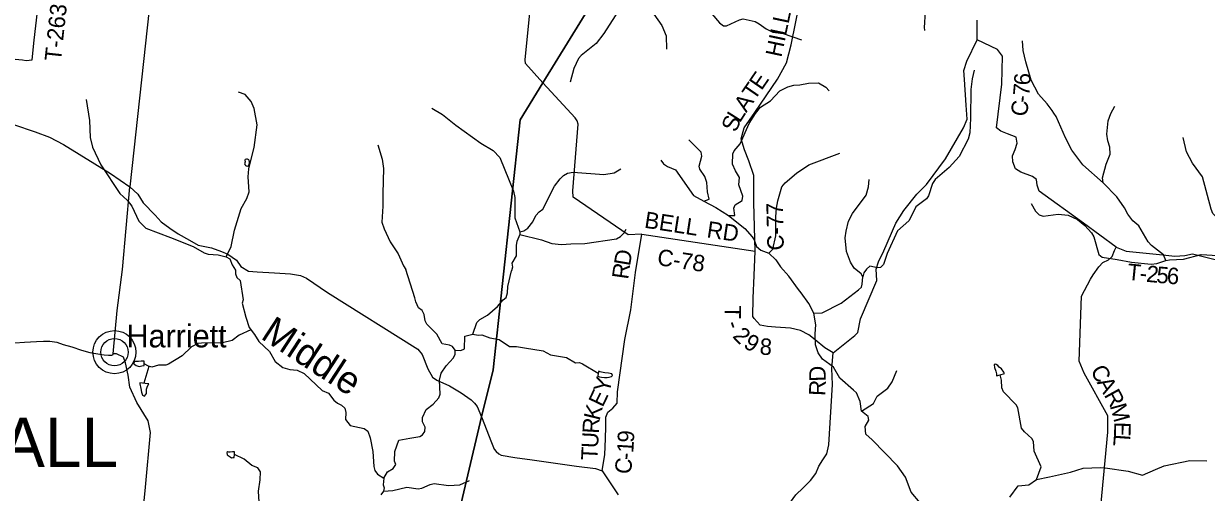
# Model space of a CAD drawing. Extents: x 1525783 to 1900577, y 218250 to 627376.
# Drawn here: x 1686297 to 1707878, y 407202 to 415754 of the extents above; entities that cross this region are included whole.
import ezdxf

# ---------------------------------------------------------------- set-up
doc = ezdxf.new("R2010")
doc.units = 0
for name, color, linetype in [('GM_X_County_Road', 7, 'Continuous'), ('GM_X_County_Road_Text', 7, 'Continuous'), ('GM_X_Minor_Lake', 7, 'Continuous'), ('GM_X_Minor_River', 7, 'Continuous'), ('GM_X_Minor_River_Text', 7, 'Continuous'), ('GM_X_State_Route', 7, 'Continuous'), ('GM_X_Township', 7, 'Continuous'), ('GM_X_Township_Road', 7, 'Continuous'), ('GM_X_Township_Road_Text', 7, 'Continuous'), ('GM_X_Township_Text', 7, 'Continuous'), ('GM_X_Unincorporated', 7, 'Continuous'), ('GM_X_Unincorporated_Location', 7, 'Continuous'), ('GM_X_Unincorporated_Text', 7, 'Continuous')]:
    doc.layers.add(name, color=color, linetype=linetype)

msp = doc.modelspace()

# ---------------------------------------------------------------- linework, layer by layer
at = {"layer": 'GM_X_County_Road'}
for points in [[(1695922, 414510), (1695772, 414672), (1695455, 415030), (1695450, 415092), (1695544, 416074), (1695641, 417095), (1695592, 417148), (1694627, 417269), (1694779, 418524), (1694799, 418859), (1694750, 418990), (1694323, 419546), (1692590, 421859)], [(1699644, 411605), (1699623, 412489), (1699619, 412983), (1699529, 413250), (1699452, 413451), (1699391, 413651), (1699445, 413854), (1699642, 414132), (1700054, 414743), (1700219, 415040), (1700299, 415367), (1700476, 416244)], [(1683229, 415931), (1683600, 415673), (1683898, 415507), (1684581, 415018), (1684679, 414918), (1684821, 414800), (1684888, 414749), (1684947, 414698), (1685278, 414411), (1685698, 414044), (1685829, 413971), (1686112, 413914), (1686509, 413780), (1686769, 413685), (1687024, 413547), (1687879, 413021), (1688235, 412775)], [(1705874, 406102), (1706079, 408301), (1706080, 408599), (1705647, 409379), (1705556, 409594), (1705599, 410784), (1705761, 411092), (1705811, 411173), (1705917, 411319), (1705987, 411394), (1706090, 411447), (1706160, 411508), (1706200, 411617), (1706232, 411679), (1705635, 412112), (1704826, 412697), (1704789, 412807), (1704777, 412909), (1704708, 412963), (1704490, 413043), (1704397, 413103), (1704346, 413231), (1704341, 413341), (1704392, 413456), (1704428, 413572), (1704407, 413683), (1704248, 413743), (1704127, 413792), (1704050, 413856), (1704148, 414652), (1704156, 415159), (1704064, 415280), (1703696, 415457), (1703693, 415819)], [(1696852, 407597), (1696903, 407893), (1696917, 408177), (1696922, 408404), (1696923, 408574), (1696956, 408667), (1697046, 408737), (1697129, 408832), (1697136, 409037), (1697268, 409989), (1697377, 410533), (1697460, 411211), (1697578, 411916), (1697329, 411902), (1696327, 412591), (1696319, 412702), (1696417, 413923), (1696398, 413982), (1696358, 414036), (1695922, 414510)], [(1689376, 402305), (1689315, 402509), (1689280, 402641), (1689079, 403395), (1688943, 403934), (1688868, 404164), (1688526, 404763), (1688383, 405107), (1688311, 405205), (1688519, 407298), (1688611, 408295), (1688572, 408507), (1688365, 408841), (1688235, 409123), (1688204, 409341), (1688156, 409567), (1688118, 409667), (1687991, 409731), (1687933, 409730), (1688006, 410518), (1688100, 411267), (1688235, 412775)], [(1697578, 411916), (1699644, 411605)]]:
    msp.add_lwpolyline(points, dxfattribs=at)
at = {"layer": 'GM_X_Minor_Lake'}
for points in [[(1690332, 413263), (1690334, 413253), (1690340, 413243), (1690336, 413229), (1690332, 413219), (1690330, 413209), (1690328, 413197), (1690336, 413177), (1690348, 413167), (1690358, 413163), (1690370, 413161), (1690382, 413157), (1690400, 413161), (1690404, 413171), (1690410, 413189), (1690414, 413199), (1690416, 413211), (1690418, 413221), (1690416, 413231), (1690414, 413249), (1690412, 413259), (1690404, 413269), (1690380, 413281), (1690362, 413281)], [(1690362, 413281), (1690340, 413274), (1690332, 413263)], [(1688498, 409547), (1688497, 409593), (1688441, 409597), (1688393, 409592), (1688345, 409592), (1688315, 409588), (1688310, 409548), (1688352, 409514), (1688406, 409497), (1688452, 409513), (1688482, 409519)], [(1688482, 409519), (1688496, 409518), (1688498, 409547)], [(1696783, 409376), (1696772, 409325), (1696806, 409312), (1696844, 409306), (1696894, 409297), (1696946, 409299), (1696982, 409302), (1697022, 409316), (1697040, 409334), (1697030, 409364), (1696969, 409379), (1696903, 409381), (1696839, 409396), (1696815, 409402), (1696795, 409416)], [(1696795, 409416), (1696783, 409376)], [(1704116, 409349), (1704194, 409370), (1704182, 409396), (1704137, 409456), (1704099, 409487), (1704071, 409515), (1704043, 409535), (1704022, 409542), (1704009, 409532), (1704013, 409480), (1704034, 409413), (1704046, 409363), (1704051, 409331)], [(1688514, 409190), (1688417, 409198), (1688419, 409181)], [(1688419, 409181), (1688436, 409097), (1688447, 409031), (1688466, 408978), (1688500, 408958), (1688539, 409006), (1688541, 409084), (1688556, 409142), (1688580, 409183), (1688514, 409190)], [(1704051, 409331), (1704116, 409349)], [(1690146, 407893), (1690142, 407941), (1690108, 407939), (1690068, 407938), (1690040, 407938), (1690022, 407940), (1690006, 407930), (1690008, 407884), (1690050, 407864), (1690067, 407852), (1690091, 407833), (1690117, 407837)], [(1690117, 407837), (1690141, 407840), (1690146, 407893)]]:
    msp.add_lwpolyline(points, dxfattribs=at)
at = {"layer": 'GM_X_Minor_River'}
for points in [[(1702119, 419487), (1702102, 419417), (1702264, 418875), (1702426, 418559), (1702534, 418306), (1702783, 417903), (1702845, 417667), (1702853, 417550), (1702819, 417483), (1702721, 417362), (1702664, 417245), (1702653, 417060), (1702734, 416802), (1702731, 416742), (1702671, 416537), (1702652, 416386), (1702659, 416308), (1702712, 416131), (1702739, 415891), (1702737, 415769), (1702731, 415691), (1702736, 415629)], [(1698814, 417899), (1698716, 417809), (1698720, 417534), (1698813, 417354), (1698859, 417221), (1698836, 417042), (1698848, 416974), (1698965, 416689), (1698979, 416580), (1698952, 416408), (1698841, 416079), (1698832, 416003), (1698855, 415933), (1698992, 415768), (1699065, 415716), (1699125, 415713), (1699358, 415827), (1699424, 415842), (1699648, 415794), (1699719, 415751), (1699846, 415662), (1699965, 415602), (1700153, 415574), (1700490, 415458)], [(1698720, 417534), (1698605, 417360), (1698418, 417126), (1698035, 416718), (1697964, 416653), (1697522, 416490), (1697406, 416392), (1697197, 416069), (1696881, 415575), (1696741, 415391), (1696469, 415171), (1696424, 415120), (1696338, 414935), (1696271, 414685)], [(1697964, 416653), (1697832, 416547), (1697630, 416282), (1697595, 416210), (1697588, 416156), (1697607, 416100), (1697794, 415930), (1697945, 415720), (1698019, 415532), (1698025, 415292)], [(1707140, 411431), (1707093, 411536), (1706880, 411709), (1706819, 411776), (1706648, 412066), (1706536, 412154), (1706446, 412276), (1706386, 412396), (1706245, 412593), (1705996, 412852), (1705627, 413180), (1705421, 413448), (1705307, 413669), (1705136, 414059), (1705095, 414120), (1705064, 414171), (1704976, 414293), (1704817, 414470), (1704684, 414725), (1704584, 415058), (1704535, 415265), (1704521, 415440)], [(1703639, 414908), (1703602, 414746), (1703582, 414554), (1703574, 414031), (1703565, 413760), (1703529, 413644), (1703366, 413330), (1703186, 413131), (1702932, 412909), (1702882, 412838), (1702808, 412612), (1702771, 412561), (1702577, 412412), (1702521, 412296), (1702446, 412157), (1702240, 411972), (1702052, 411562), (1701988, 411359), (1701929, 411306), (1701877, 411297), (1701737, 411327), (1701674, 411272), (1701630, 411205), (1701609, 411137)], [(1699158, 412254), (1699271, 412256), (1699253, 412387), (1699280, 412451), (1699410, 412530), (1699418, 412605), (1699347, 412816), (1699360, 412947), (1699288, 413068), (1699232, 413192), (1699236, 413380), (1699259, 413432), (1699369, 413560), (1699535, 413930), (1699609, 414048), (1699652, 414113), (1699741, 414230), (1699924, 414349), (1700097, 414526), (1700239, 414600), (1700352, 414632), (1700458, 414638), (1700619, 414669), (1700802, 414674), (1700933, 414598), (1700993, 414528)], [(1687438, 414373), (1687497, 413987), (1687513, 413679), (1687554, 413500), (1687706, 413178), (1688051, 412655), (1688185, 412534), (1688273, 412424), (1688401, 412153), (1688524, 412022), (1688978, 411851), (1689390, 411688), (1689588, 411572), (1689662, 411546), (1689848, 411537), (1689992, 411502), (1690062, 411461), (1690100, 411352), (1690161, 411255)], [(1689992, 411502), (1690086, 411691), (1690146, 411987), (1690267, 412382), (1690369, 412567), (1690413, 412686), (1690393, 412961), (1690407, 413108), (1690453, 413309), (1690501, 413497), (1690561, 413909), (1690506, 414209), (1690448, 414337), (1690337, 414461), (1690219, 414505)], [(1693746, 414213), (1693942, 414099), (1694183, 413900), (1694640, 413571), (1694862, 413439), (1694988, 413314), (1695233, 412700), (1695257, 412585), (1695262, 412210), (1695352, 411957), (1695351, 411907), (1695296, 411780), (1695283, 411710), (1695285, 411515), (1695207, 411384), (1695217, 411312), (1695196, 411242)], [(1705996, 412852), (1705981, 412940), (1706048, 413192), (1706120, 413373), (1706116, 413500), (1706080, 413617), (1706064, 413737), (1706089, 413982), (1706138, 414117), (1706210, 414250)], [(1692757, 413545), (1692841, 413284), (1692865, 413109), (1692849, 412658), (1692854, 412422), (1692833, 412135), (1692873, 412012), (1692985, 411775), (1693131, 411552), (1693227, 411336), (1693272, 411269)], [(1698706, 412517), (1698807, 412553), (1698774, 412688), (1698765, 412857), (1698725, 412968), (1698633, 413102), (1698626, 413152), (1698672, 413336), (1698657, 413407), (1698435, 413637)], [(1708341, 411440), (1708371, 411453), (1708372, 411640), (1708354, 411712), (1708309, 411787), (1708201, 411892), (1708153, 412105), (1708112, 412170), (1707996, 412290), (1707963, 412367), (1707808, 412962), (1707628, 413208), (1707516, 413414), (1707453, 413680)], [(1699893, 411567), (1699967, 411642), (1700023, 411884), (1700022, 412229), (1700037, 412387), (1700058, 412521), (1700132, 412774), (1700190, 412848), (1700400, 413026), (1700627, 413179), (1701187, 413393)], [(1695352, 411957), (1695424, 411974), (1695497, 412023), (1695586, 412140), (1695644, 412255), (1695703, 412322), (1695770, 412369), (1695985, 412787), (1696084, 412923), (1696147, 412984), (1696218, 413025), (1696322, 413045), (1696883, 413005), (1697072, 413032), (1697192, 413104)], [(1697924, 413263), (1697973, 413194), (1698046, 413145), (1698192, 413090), (1698522, 412619), (1698706, 412517), (1698925, 412401), (1699158, 412254), (1699457, 412014), (1699590, 411867), (1699625, 411808), (1699669, 411691), (1699746, 411622), (1699893, 411567), (1700023, 411446), (1700107, 411318), (1700260, 411147)], [(1701609, 411137), (1701580, 411188), (1701454, 411294), (1701386, 411400), (1701309, 411596), (1701290, 411845), (1701304, 411971), (1701348, 412153), (1701420, 412290), (1701669, 412626), (1701712, 412780), (1701723, 412910)], [(1704681, 412474), (1704761, 412330), (1704828, 412269), (1704900, 412244), (1705175, 412277), (1705355, 412262), (1705526, 412180), (1705662, 412072), (1705780, 411937), (1705823, 411864), (1705915, 411543), (1705976, 411492), (1706248, 411451), (1706514, 411400), (1706870, 411364), (1706972, 411378), (1707140, 411431), (1707208, 411446), (1707461, 411459), (1707785, 411540), (1708088, 411526)], [(1695351, 411907), (1695746, 411810), (1695935, 411744), (1696109, 411727), (1696280, 411734), (1696537, 411746), (1697113, 411827), (1697188, 411870), (1697256, 411935), (1697289, 412003)], [(1690161, 411255), (1690162, 411187), (1690190, 411125), (1690249, 411066), (1690300, 410718), (1690287, 410652), (1690354, 410399), (1690412, 410210), (1690511, 410085), (1690586, 409956), (1690784, 409774), (1690888, 409589), (1691028, 409481), (1691156, 409446), (1691286, 409431), (1691417, 409373), (1691743, 409060), (1691859, 409011), (1691955, 408886), (1692021, 408827), (1692096, 408794), (1692156, 408738), (1692175, 408661), (1692170, 408531), (1692252, 408421), (1692512, 408370), (1692575, 408319), (1692618, 408199), (1692671, 407950), (1692687, 407676), (1692708, 407599), (1692753, 407533), (1692868, 407462), (1692857, 407338), (1692876, 407287), (1692866, 407226), (1692815, 407156)], [(1692868, 407462), (1692937, 407579), (1693040, 407638), (1693088, 407710), (1693065, 407772), (1693067, 407950), (1693143, 408153), (1693345, 408188), (1693525, 408224), (1693575, 408251), (1693620, 408315), (1693621, 408389), (1693572, 408490), (1693572, 408568), (1693644, 408717), (1693771, 408812), (1693872, 408929), (1693900, 408993), (1693885, 409249), (1693918, 409377), (1694009, 409508), (1694139, 409655), (1694171, 409725), (1694172, 409799), (1694121, 409865), (1694065, 409888), (1693933, 409911), (1693835, 410090), (1693653, 410270), (1693624, 410330), (1693605, 410449), (1693568, 410519), (1693502, 410572), (1693454, 410680), (1693434, 410749), (1693272, 411269)], [(1694172, 409799), (1694272, 409788), (1694340, 409823), (1694348, 410051), (1694491, 410090), (1694566, 410299), (1694619, 410359), (1694758, 410435), (1694945, 410596), (1695046, 410715), (1695104, 410760), (1695127, 410840), (1695130, 410958), (1695196, 411242)], [(1702656, 407011), (1702494, 407207), (1702391, 407478), (1702243, 407686), (1701777, 408161), (1701662, 408262), (1701655, 408404), (1701720, 408521), (1701707, 408588), (1701586, 408681), (1701562, 408863), (1701496, 409020), (1701438, 409069), (1701187, 409285), (1701073, 409484), (1700876, 409632), (1700794, 409749), (1700749, 409894), (1700737, 410092), (1700755, 410258), (1700717, 410473), (1700623, 410648), (1700485, 410843), (1700436, 410906), (1700260, 411147)], [(1700717, 410473), (1700865, 410479), (1701212, 410652), (1701532, 410897), (1701583, 410945), (1701597, 410998), (1701609, 411137)], [(1690444, 410170), (1690229, 410068), (1690100, 409971), (1689928, 409931), (1689543, 409922), (1689477, 409921), (1689360, 409856), (1689189, 409692), (1688943, 409540), (1688893, 409525), (1688757, 409520), (1688635, 409485), (1688574, 409502), (1688498, 409549)], [(1694491, 410090), (1694588, 410071), (1694658, 410078), (1694801, 410023), (1694973, 409991), (1695161, 409861), (1695293, 409862), (1695435, 409838), (1695776, 409783), (1695909, 409713), (1696200, 409664), (1696367, 409563), (1696437, 409570), (1696497, 409545), (1696783, 409376)], [(1688583, 409499), (1688492, 409192)], [(1701586, 408681), (1701803, 408823), (1701874, 408960), (1702066, 409102), (1702147, 409220), (1702231, 409423)], [(1704778, 407435), (1704862, 407670), (1704737, 407953), (1704721, 408130), (1704693, 408182), (1704559, 408309), (1704505, 408372), (1704437, 408747), (1704408, 408799), (1704176, 409036), (1704143, 409108), (1704137, 409250), (1704118, 409349)], [(1691138, 406091), (1690997, 406323), (1690792, 406570), (1690630, 406823), (1690595, 407026), (1690585, 407226), (1690615, 407428), (1690618, 407576), (1690573, 407647), (1690459, 407692), (1690323, 407805), (1690146, 407893)], [(1704295, 407115), (1704447, 407322), (1704641, 407338), (1704778, 407435), (1705014, 407488), (1705396, 407571), (1705631, 407642), (1705946, 407653), (1706034, 407648), (1706451, 407586), (1706714, 407516), (1706953, 407621), (1707107, 407686), (1707576, 407785), (1707889, 407776)], [(1692866, 407226), (1693032, 407234), (1693290, 407297), (1693496, 407269), (1693560, 407277), (1693716, 407347), (1693788, 407362), (1694050, 407326), (1694255, 407340), (1694430, 407420)]]:
    msp.add_lwpolyline(points, dxfattribs=at)
at = {"layer": 'GM_X_State_Route'}
msp.add_lwpolyline([(1689016, 419921), (1688235, 412775), (1688381, 412646), (1688480, 412485), (1688694, 412260), (1688804, 412141), (1688964, 412021), (1689114, 411920), (1689322, 411803), (1689479, 411715), (1689727, 411666), (1689906, 411596), (1690023, 411551), (1690183, 411437), (1690261, 411325), (1690400, 411236), (1690558, 411225), (1690875, 411210), (1691165, 411192), (1691347, 411162), (1691461, 411113), (1691842, 410848), (1693491, 409817), (1693567, 409720), (1693670, 409455), (1693760, 409303), (1693839, 409248), (1694068, 409145), (1694283, 409021), (1694465, 408888), (1694522, 408831), (1694570, 408766), (1694651, 408579), (1694832, 408111), (1694885, 407992), (1694922, 407945), (1694968, 407906), (1695011, 407882), (1695261, 407840), (1695575, 407795), (1696386, 407683), (1696734, 407635), (1696852, 407597), (1697148, 407158)], dxfattribs=at)
at = {"layer": 'GM_X_Township'}
for points in [[(1699164, 420184), (1695772, 414672), (1695360, 414002), (1694863, 409438), (1694651, 408579), (1692963, 401404), (1692960, 401391), (1692916, 400719), (1692619, 395862), (1688475, 399440), (1688322, 399564), (1688208, 399673), (1687479, 400030), (1682729, 402947), (1680396, 404440), (1678915, 405396), (1678615, 405583), (1678537, 406652), (1678285, 411417), (1677923, 418276)], [(1708828, 383819), (1700474, 382353), (1699796, 382245), (1691630, 380967), (1691819, 383865), (1692250, 390483), (1692619, 395862), (1692916, 400719), (1692960, 401391), (1692963, 401404), (1694651, 408579), (1694863, 409438), (1695360, 414002), (1695772, 414672), (1699164, 420184)]]:
    msp.add_lwpolyline(points, dxfattribs=at)
at = {"layer": 'GM_X_Township_Road'}
for points in [[(1684947, 414698), (1685292, 414832), (1685549, 414918), (1685672, 414968), (1685738, 415034), (1685790, 415109), (1685938, 415126), (1686274, 415092), (1686342, 415082), (1686454, 415094), (1686489, 415454), (1686651, 416873), (1686742, 417655), (1686764, 417733), (1687056, 417730), (1687274, 417707), (1687376, 417716), (1687467, 417811), (1687674, 418187), (1688289, 419091), (1688579, 419532), (1688747, 419737), (1688884, 419862), (1689016, 419921)], [(1701066, 409750), (1701461, 410065), (1701521, 410117), (1701565, 410367), (1701866, 411068), (1701850, 411275), (1701897, 411410), (1701994, 411609), (1702210, 412113), (1702356, 412344), (1702593, 412644), (1702770, 412818), (1703118, 413290), (1703449, 413852), (1703511, 414011), (1703498, 414270), (1703467, 414734), (1703450, 414899), (1703505, 415072), (1703696, 415457)], [(1701066, 409750), (1700915, 409840), (1700740, 409985), (1700623, 410076), (1700472, 410157), (1700290, 410196), (1700015, 410219), (1699871, 410230), (1699737, 410255), (1699629, 410376), (1699604, 410409), (1699608, 410743), (1699625, 411160), (1699644, 411605)], [(1706232, 411679), (1706414, 411604), (1707082, 411534), (1707302, 411513), (1707484, 411525), (1707623, 411554), (1708061, 411443)], [(1686134, 409932), (1686312, 409945), (1686532, 409954), (1686658, 409959), (1686776, 409962), (1686905, 409940), (1687021, 409899), (1687178, 409856), (1687352, 409799), (1687507, 409756), (1687685, 409725), (1687765, 409713), (1687847, 409704), (1687905, 409706), (1687933, 409720), (1687933, 409730)], [(1699218, 405001), (1699277, 405175), (1699408, 405373), (1699495, 405582), (1699649, 405787), (1699776, 405986), (1699853, 406215), (1699934, 406404), (1700076, 406665), (1700181, 406851), (1700260, 406979), (1700385, 407156), (1700523, 407284), (1700654, 407419), (1700753, 407546), (1700807, 407682), (1700878, 407795), (1700951, 407908), (1700990, 408072), (1701055, 409173), (1701041, 409464), (1701066, 409750)]]:
    msp.add_lwpolyline(points, dxfattribs=at)
at = {"layer": 'GM_X_Unincorporated'}
for radius in [393, 249]:
    msp.add_circle((1687954, 409760), radius, dxfattribs=at)
at = {"layer": 'GM_X_Unincorporated_Location'}
msp.add_line((1687954, 409760), (1687954, 409760), dxfattribs=at)

# ---------------------------------------------------------------- texts
at = {"layer": 'GM_X_County_Road_Text'}
for s, rotation, p in [('HILL', 78.008, (1700123, 415129)), ('E', 55.531, (1699760, 414523)), ('6', 87.2931, (1704666, 414625)), ('T', 55.529, (1699633, 414338)), ('7', 84.6729, (1704647, 414426)), ('A', 55.5532, (1699483, 414120)), ('-', 83.7955, (1704634, 414299)), ('L', 57.6544, (1699365, 413933)), ('C', 83.5387, (1704606, 414052)), ('S', 68.6353, (1699298, 413758)), ('C-77', 91.3713, (1700169, 411620)), ('BELL', 351.1709, (1697611, 412033)), ('RD', 351.5902, (1698750, 411857)), ('D', 80.4185, (1697361, 411321)), ('C-78', 351.3837, (1697845, 411352)), ('R', 81.898, (1697326, 411079)), ('C', 298.8207, (1705754, 409427)), ('Y', 75.2793, (1696979, 409001)), ('A', 299.2194, (1705874, 409209)), ('E', 64.3281, (1696861, 408741)), ('R', 298.7893, (1706003, 408980)), ('K', 76.1546, (1696803, 408500)), ('M', 285.558, (1706115, 408780)), ('R', 86.7784, (1696791, 408268)), ('9', 87.6153, (1697432, 408105)), ('E', 268.6971, (1706199, 408490)), ('U', 87.1683, (1696778, 408005)), ('1', 86.3986, (1697420, 407914)), ('L', 265.8738, (1706194, 408269)), ('T', 87.1703, (1696767, 407781)), ('-', 84.6365, (1697408, 407781)), ('C', 81.3058, (1697369, 407519))]:
    msp.add_text(s, height=300, rotation=rotation, dxfattribs=at).set_placement(p)
at = {"layer": 'GM_X_Minor_River_Text'}
msp.add_text('Middle', height=500, rotation=326.8718, dxfattribs=at).set_placement((1690602, 410021))
at = {"layer": 'GM_X_Township_Road_Text'}
for s, rotation, p in [('T-263', 83.8709, (1686976, 415058)), ('T', 354.2173, (1706425, 411081)), ('2', 354.3632, (1706772, 411046)), ('-', 354.2572, (1706649, 411058)), ('5', 354.8114, (1706958, 411028)), ('6', 356.1873, (1707150, 411010)), ('T', 269.3786, (1699088, 410615)), ('-', 288.7107, (1699103, 410282)), ('2', 314.4888, (1699219, 410041)), ('9', 329.062, (1699414, 409858)), ('8', 356.6817, (1699721, 409717)), ('D', 91.7744, (1700935, 409227)), ('R', 87.7279, (1700925, 408958))]:
    msp.add_text(s, height=300, rotation=rotation, dxfattribs=at).set_placement(p)
at = {"layer": 'GM_X_Township_Text'}
msp.add_text('MARSHALL', height=900, rotation=0, dxfattribs=at).set_placement((1681536, 407663))
at = {"layer": 'GM_X_Unincorporated_Text'}
msp.add_text('Harriett', height=417, rotation=0, dxfattribs=at).set_placement((1688173, 409847))

doc.saveas('drawing.dxf')
